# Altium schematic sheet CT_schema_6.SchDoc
size 296 x 239 mm
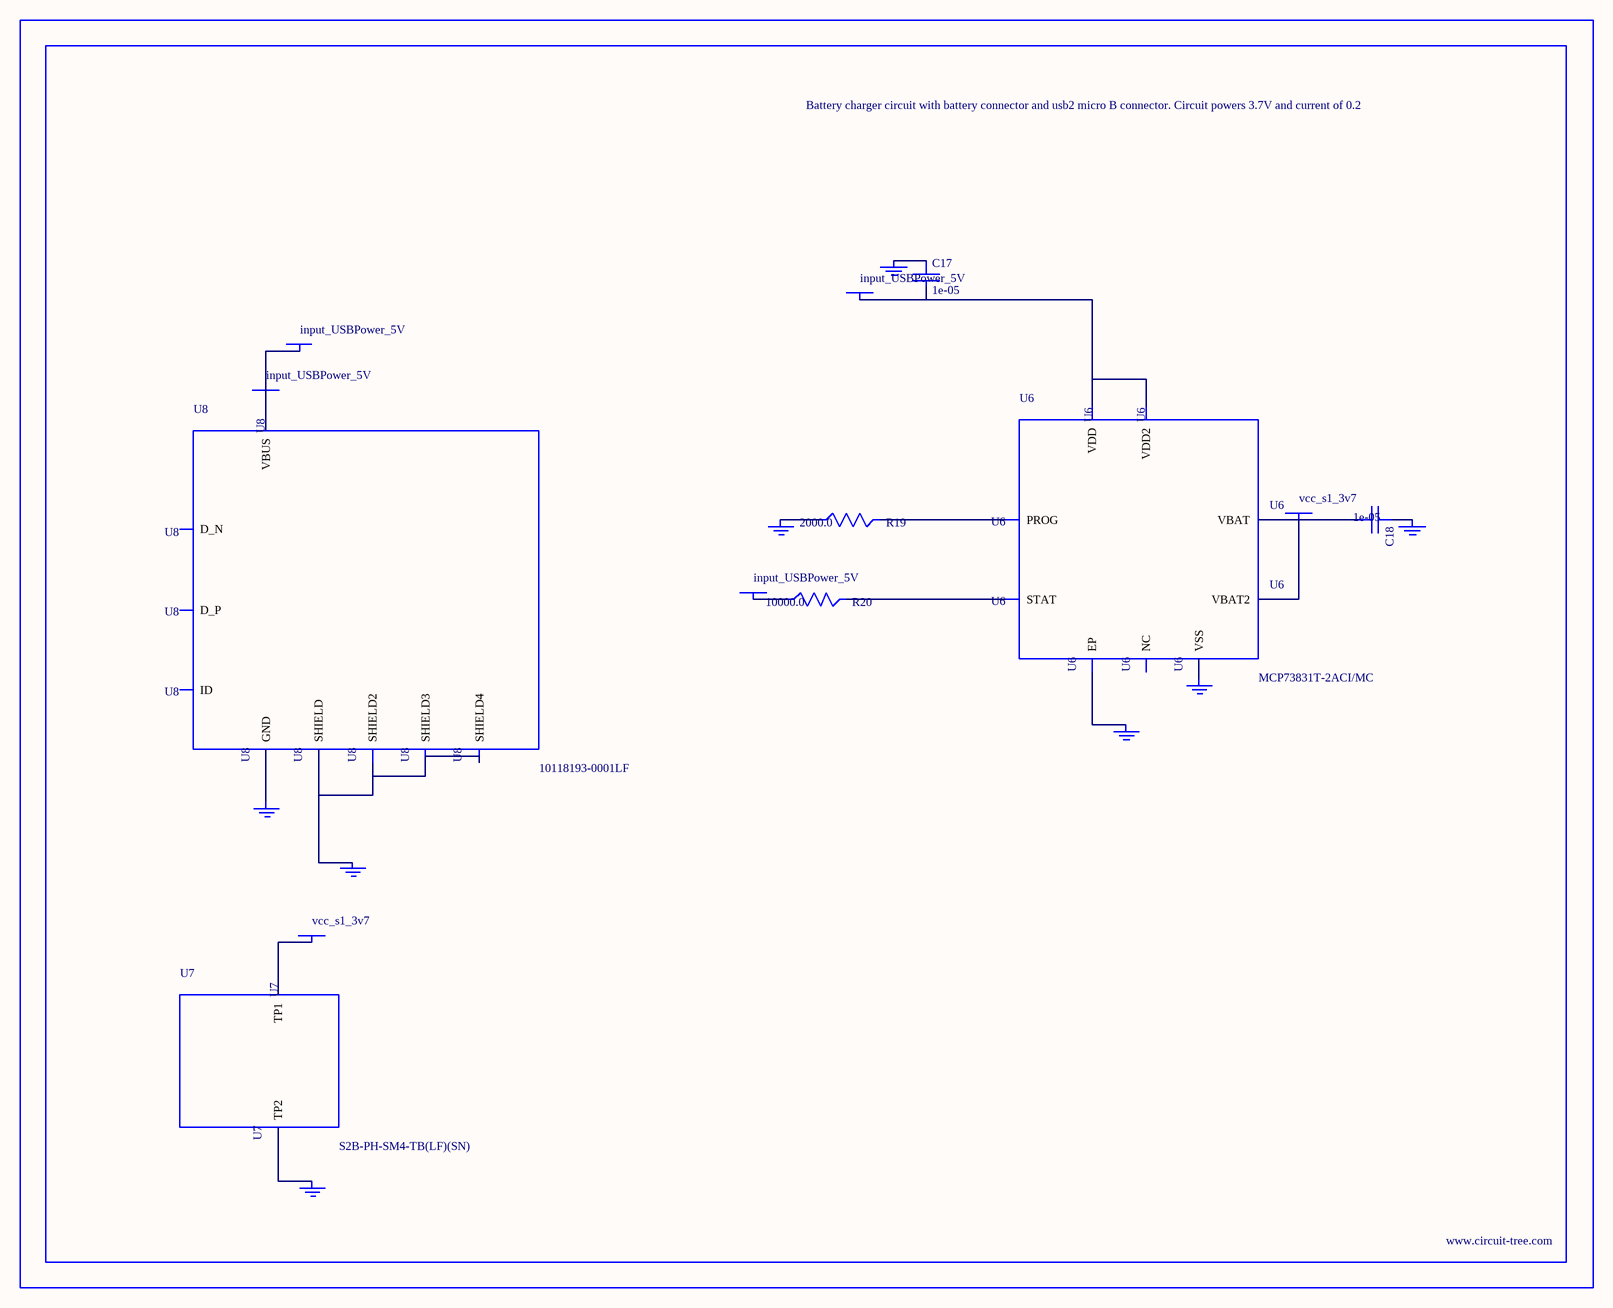
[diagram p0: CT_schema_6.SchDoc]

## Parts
BORDER5  (no value)
C17  1e-05  [C1206]
C18  1e-05  [C1206]
GND_INSTANCE_5_0  (no value)
GND_INSTANCE_5_1  (no value)
GND_INSTANCE_5_2  (no value)
GND_INSTANCE_5_3  (no value)
GND_INSTANCE_5_4  (no value)
GND_INSTANCE_5_5  (no value)
GND_INSTANCE_5_6  (no value)
GND_INSTANCE_5_7  (no value)
POWER_INSTANCE_5_0  input_USBPower_5V
POWER_INSTANCE_5_1  input_USBPower_5V
POWER_INSTANCE_5_2  vcc_s1_3v7
POWER_INSTANCE_5_3  vcc_s1_3v7
POWER_INSTANCE_5_4  input_USBPower_5V
POWER_INSTANCE_5_5  input_USBPower_5V
R19  2000.0  [R0603]
R20  10000.0  [R0603]
U6  MCP73831T-2ACI/MC  [DFN8_2X3MC]
U7  S2B-PH-SM4-TB(LF)(SN)  [JST-2-SMD]
U8  10118193-0001LF  [FCI_10118193-0001LF]

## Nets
NetC17_1: C17.1 GND_INSTANCE_5_0.0(GND)
NetC17_2: C17.2 POWER_INSTANCE_5_0.0(PWR) U6.1(VDD) U6.2(VDD2)
NetC18_1: C18.1 GND_INSTANCE_5_1.0(GND)
NetC18_2: C18.2 POWER_INSTANCE_5_2.0(PWR) U6.3(VBAT) U6.4(VBAT2)
NetGND_INSTANCE_5_2_0: GND_INSTANCE_5_2.0(GND) R19.1
NetGND_INSTANCE_5_3_0: GND_INSTANCE_5_3.0(GND) U6.9(EP)
NetGND_INSTANCE_5_4_0: GND_INSTANCE_5_4.0(GND) U6.6(VSS)
NetGND_INSTANCE_5_5_0: GND_INSTANCE_5_5.0(GND) U7.2(TP2)
NetGND_INSTANCE_5_6_0: GND_INSTANCE_5_6.0(GND) U8.6(SHIELD) U8.7(SHIELD2) U8.8(SHIELD3) U8.9(SHIELD4)
NetGND_INSTANCE_5_7_0: GND_INSTANCE_5_7.0(GND) U8.5(GND)
NetPOWER_INSTANCE_5_1_0: POWER_INSTANCE_5_1.0(PWR) R20.1
NetPOWER_INSTANCE_5_3_0: POWER_INSTANCE_5_3.0(PWR) U7.1(TP1)
NetPOWER_INSTANCE_5_4_0: POWER_INSTANCE_5_4.0(PWR) POWER_INSTANCE_5_5.0(PWR) U8.1(VBUS)
NetR19_2: R19.2 U6.8(PROG)
NetR20_2: R20.2 U6.5(STAT)

Not connected (* = marked no-connect by the designer): U6 7(NC); U8 2(D_N) 3(D_P) 4(ID)

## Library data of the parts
BORDER5 = BORDER_PAGE5
C17 C18 = C1206C106K3RACTU
GND_INSTANCE_5_0-GND_INSTANCE_5_7 = GND
POWER_INSTANCE_5_0-POWER_INSTANCE_5_5 = PWR
R19 = RC0603JR-072KL
R20 = RC0603JR-0710KL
